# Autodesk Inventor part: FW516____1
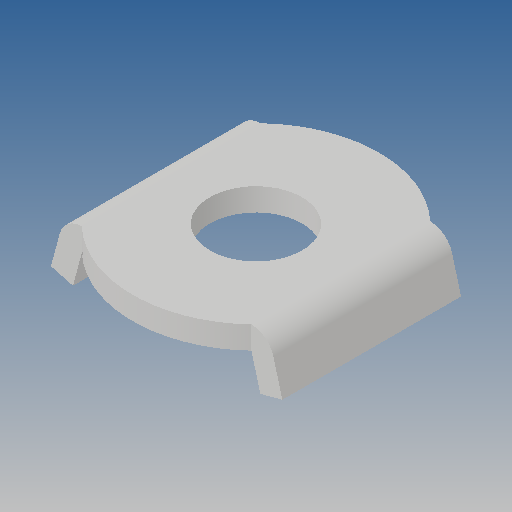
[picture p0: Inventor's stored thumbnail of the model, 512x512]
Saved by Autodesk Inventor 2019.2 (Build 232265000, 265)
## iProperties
Created: 2012-09
Part Number: FW516____1
Material: Ogólny
Document SubType Name: Modeling
Designer: CADENGINEERING4
Density: 1 g/cm^3
Appearance: Domyślna
Author: CADENGINEERING4
Revision Number: ÈÎºÎ
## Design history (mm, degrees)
feature "NONE"
node "Bryła1"
